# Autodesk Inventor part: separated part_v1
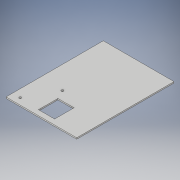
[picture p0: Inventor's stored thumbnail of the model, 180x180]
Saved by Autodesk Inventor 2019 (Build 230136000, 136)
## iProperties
Created: 2019-08
Part Number: separated part_v1
Material: 常规
Document SubType Name: Modeling
Designer: YOGA3
Density: 1 g/cm^3
Appearance: 默认
Author: YOGA3
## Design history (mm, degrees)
sketch "草图1"
  geometry: L1 (54.5, 75)-(-54.5, 75); L2 (-54.5, 75)-(-54.5, -75); L3 (-54.5, -75)-(54.5, -75); L4 (54.5, -75)-(54.5, 75); L5 (54.5, 75)-(-54.5, -75); L6 (-54.5, 75)-(54.5, -75); 1 further point
  constraints: 12 end point, 2 midpoint, 2 parallel, 1 horizontal, 1 perpendicular
  dimensions: "d0" = 109 distance of L3.end L2.end; "d1" = 150 distance of L2.end L1.end
extrude "拉伸1" new body sketch "草图1" distance "d2" = 2; taper "d3" = 0 deg
sketch "草图2"
  geometry: L1 (-54.5, -75)-(54.5, -75) reference; L2 (-54.5, 75)-(-54.5, -75) reference; C1 r 1.75 at (-42.5, -65); C2 r 1.75 at (-19.5, -23); 1 further point
  constraints: 2 centre point
  dimensions: "d12" = 3.5 diameter of C1; "d13" = 3.5 diameter of C2; "d14" = 12 distance from line of L2 C1.centre; "d15" = 35 distance from line of L2 C2.centre; "d16" = 10 distance from line of L1 C1.centre; "d17" = 52 distance from line of L1 C2.centre
extrude "拉伸2" cut sketch "草图2" distance "d10" = 2; taper "d11" = 0 deg
sketch "草图3"
  geometry: L1 (12.5, -67)-(-12.5, -67); L2 (-12.5, -67)-(-12.5, -37); L3 (-12.5, -37)-(12.5, -37); L4 (12.5, -37)-(12.5, -67); L5 (12.5, -67)-(-12.5, -37); L6 (-12.5, -67)-(12.5, -37); L7 (-54.5, -75)-(54.5, -75) reference; 2 further points
  constraints: 12 end point, 2 midpoint, 2 parallel, 1 horizontal, 1 perpendicular
  dimensions: "d18" = 25 distance of L2.end L3.end; "d19" = 30 distance of L3.end L1.start; "d20" = 8 distance between parallel lines of L7 L1
extrude "拉伸3" cut sketch "草图3" distance "d21" = 10; taper "d22" = 0 deg
node "实体1"
